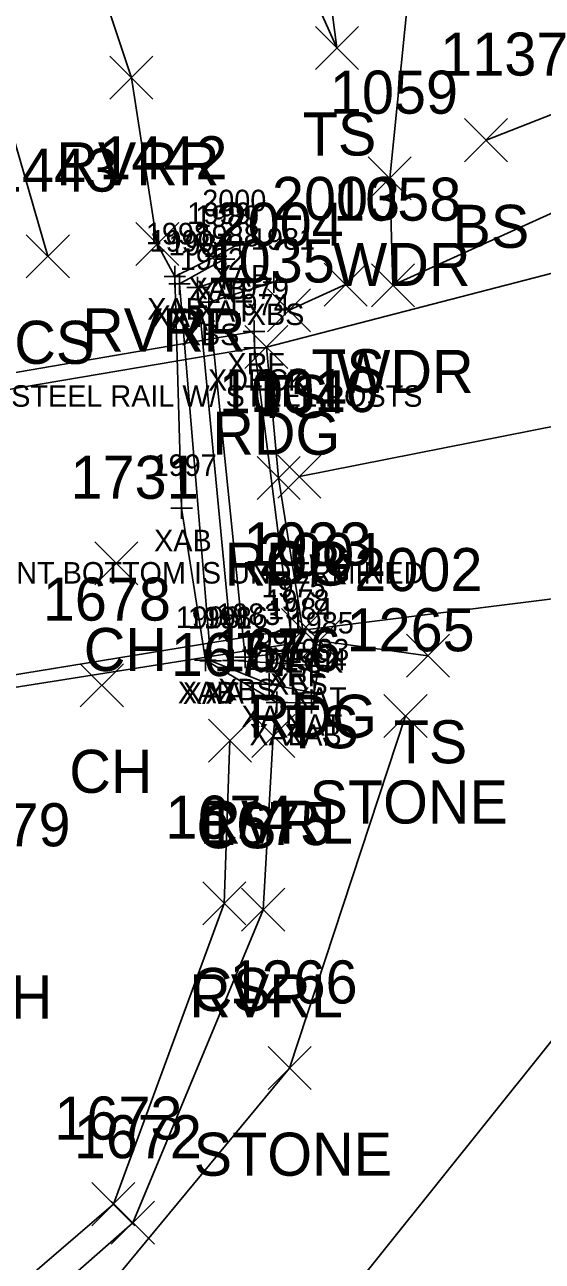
# Model space of a CAD drawing. Extents: x 1621633 to 1624015, y 417863 to 420979.
# Drawn here: x 1621985 to 1622009, y 418067.9 to 418125.3 of the extents above; entities that cross this region are included whole.
import ezdxf

# ---------------------------------------------------------------- set-up
doc = ezdxf.new("R2010")
doc.units = 0
for name, color, linetype in [('B_A', 7, 'Continuous'), ('B_C', 7, 'Continuous'), ('B_I', 7, 'Continuous'), ('B_TIC', 7, 'Continuous'), ('BELB', 7, 'Continuous'), ('BR', 7, 'Continuous'), ('BSE', 7, 'Continuous'), ('BSUBM', 7, 'Continuous'), ('L_A', 7, 'Continuous'), ('L_I', 7, 'Continuous'), ('L_TIC', 7, 'Continuous'), ('LASF', 7, 'Continuous'), ('LAWA', 7, 'Continuous'), ('LAWE', 7, 'Continuous'), ('LELB', 7, 'Continuous'), ('P_A', 7, 'Continuous'), ('P_I', 7, 'Continuous'), ('P_TIC', 7, 'Continuous'), ('PEU', 7, 'Continuous'), ('PRC', 7, 'Continuous'), ('RDW', 7, 'Continuous')]:
    doc.layers.add(name, color=color, linetype=linetype)

msp = doc.modelspace()

# ---------------------------------------------------------------- linework, layer by layer
at = {"layer": 'B_TIC'}
for p, q in [((1621994.992, 418115.159), (1621995.067, 418115.159)), ((1621993.888, 418114.568), (1621993.964, 418114.568)), ((1621994.261, 418114.427), (1621994.336, 418114.427)), ((1621991.966, 418113.622), (1621992.042, 418113.622)), ((1621992.185, 418113.283), (1621992.26, 418113.283)), ((1621993.024, 418113.11), (1621993.099, 418113.11)), ((1621994.28, 418113.527), (1621994.356, 418113.527)), ((1621996.565, 418113.372), (1621996.64, 418113.372)), ((1621993.546, 418112.437), (1621993.621, 418112.437)), ((1621995.644, 418111.077), (1621995.72, 418111.077)), ((1621995.667, 418110.32), (1621995.742, 418110.32)), ((1621992.283, 418102.865), (1621992.358, 418102.865)), ((1621997.34, 418097.222), (1621997.416, 418097.222)), ((1621997.521, 418096.593), (1621997.597, 418096.593)), ((1621993.385, 418095.803), (1621993.46, 418095.803)), ((1621993.635, 418095.778), (1621993.71, 418095.778)), ((1621994.683, 418095.792), (1621994.758, 418095.792)), ((1621995.239, 418095.942), (1621995.315, 418095.942)), ((1621997.65, 418096.2), (1621997.725, 418096.2)), ((1621998.648, 418095.545), (1621998.723, 418095.545)), ((1621996.352, 418094.696), (1621996.427, 418094.696)), ((1621998.437, 418094.296), (1621998.513, 418094.296)), ((1621996.706, 418093.845), (1621996.781, 418093.845)), ((1621998.32, 418093.831), (1621998.395, 418093.831))]:
    msp.add_line(p, q, dxfattribs=at)
for points in [[(1621994.988, 418114.659), (1621994.988, 418115.659)], [(1621993.885, 418114.068), (1621993.885, 418115.068)], [(1621994.257, 418113.927), (1621994.257, 418114.927)], [(1621994.488, 418115.159), (1621995.488, 418115.159)], [(1621993.385, 418114.568), (1621994.385, 418114.568)], [(1621993.757, 418114.427), (1621994.757, 418114.427)], [(1621991.463, 418113.622), (1621992.463, 418113.622)], [(1621991.963, 418113.122), (1621991.963, 418114.122)], [(1621992.181, 418112.783), (1621992.181, 418113.783)], [(1621993.02, 418112.61), (1621993.02, 418113.61)], [(1621994.277, 418113.027), (1621994.277, 418114.027)], [(1621996.561, 418112.872), (1621996.561, 418113.872)], [(1621991.681, 418113.283), (1621992.681, 418113.283)], [(1621992.52, 418113.11), (1621993.52, 418113.11)], [(1621993.777, 418113.527), (1621994.777, 418113.527)], [(1621996.061, 418113.372), (1621997.061, 418113.372)], [(1621993.042, 418112.437), (1621994.042, 418112.437)], [(1621993.542, 418111.937), (1621993.542, 418112.937)], [(1621995.641, 418110.577), (1621995.641, 418111.577)], [(1621995.141, 418111.077), (1621996.141, 418111.077)], [(1621995.663, 418109.82), (1621995.663, 418110.82)], [(1621995.163, 418110.32), (1621996.163, 418110.32)], [(1621992.279, 418102.365), (1621992.279, 418103.365)], [(1621991.779, 418102.865), (1621992.779, 418102.865)], [(1621997.337, 418096.722), (1621997.337, 418097.722)], [(1621996.837, 418097.222), (1621997.837, 418097.222)], [(1621997.518, 418096.093), (1621997.518, 418097.093)], [(1621995.236, 418095.442), (1621995.236, 418096.442)], [(1621997.018, 418096.593), (1621998.018, 418096.593)], [(1621997.646, 418095.7), (1621997.646, 418096.7)], [(1621992.881, 418095.803), (1621993.881, 418095.803)], [(1621993.131, 418095.778), (1621994.131, 418095.778)], [(1621993.381, 418095.303), (1621993.381, 418096.303)], [(1621993.631, 418095.278), (1621993.631, 418096.278)], [(1621994.179, 418095.792), (1621995.179, 418095.792)], [(1621994.679, 418095.292), (1621994.679, 418096.292)], [(1621994.736, 418095.942), (1621995.736, 418095.942)], [(1621997.146, 418096.2), (1621998.146, 418096.2)], [(1621998.644, 418095.045), (1621998.644, 418096.045)], [(1621996.348, 418094.196), (1621996.348, 418095.196)], [(1621998.144, 418095.545), (1621999.144, 418095.545)], [(1621995.848, 418094.696), (1621996.848, 418094.696)], [(1621998.434, 418093.796), (1621998.434, 418094.796)], [(1621996.703, 418093.345), (1621996.703, 418094.345)], [(1621997.934, 418094.296), (1621998.934, 418094.296)], [(1621998.316, 418093.331), (1621998.316, 418094.331)], [(1621996.203, 418093.845), (1621997.203, 418093.845)], [(1621997.816, 418093.831), (1621998.816, 418093.831)]]:
    msp.add_lwpolyline(points, dxfattribs=at)
at = {"layer": 'BELB'}
msp.add_lwpolyline([(1621972.279, 418106.356), (1621995.663, 418110.32), (1621997.337, 418097.222), (1621973.974, 418093.412)], dxfattribs=at)
at = {"layer": 'BR'}
for points in [[(1621995.641, 418111.077), (1621972.301, 418107.07)], [(1621974.113, 418092.897), (1621997.518, 418096.593)]]:
    msp.add_lwpolyline(points, dxfattribs=at)
at = {"layer": 'BSE'}
msp.add_lwpolyline([(1621996.561, 418113.372), (1621993.542, 418112.437), (1621995.236, 418095.942), (1621997.646, 418096.2)], dxfattribs=at)
at = {"layer": 'BSUBM'}
for points in [[(1621998.316, 418093.831), (1621996.703, 418093.845), (1621993.381, 418095.803), (1621992.279, 418102.865), (1621991.963, 418113.622), (1621993.885, 418114.568), (1621994.988, 418115.159)], [(1621998.644, 418095.545), (1621994.679, 418095.792), (1621993.02, 418113.11), (1621994.277, 418113.527), (1621994.257, 418114.427), (1621992.181, 418113.283), (1621993.631, 418095.778), (1621996.348, 418094.696), (1621998.434, 418094.296)], [(1621998.434, 418094.296), (1621998.644, 418095.545)]]:
    msp.add_lwpolyline(points, dxfattribs=at)
at = {"layer": 'L_TIC'}
for points in [[(1621998.493, 418123.246), (1622000.493, 418125.246)], [(1622000.493, 418123.246), (1621998.493, 418125.246)], [(1621988.945, 418121.858), (1621990.945, 418123.858)], [(1621990.945, 418121.858), (1621988.945, 418123.858)], [(1622005.415, 418118.96), (1622007.415, 418120.96)], [(1622007.415, 418118.96), (1622005.415, 418120.96)], [(1622000.944, 418117.19), (1622002.944, 418119.19)], [(1622002.944, 418117.19), (1622000.944, 418119.19)], [(1621990.148, 418114.143), (1621992.148, 418116.143)], [(1621992.148, 418114.143), (1621990.148, 418116.143)], [(1621985.067, 418113.571), (1621987.067, 418115.571)], [(1621987.067, 418113.571), (1621985.067, 418115.571)], [(1621998.891, 418112.252), (1622000.891, 418114.252)], [(1622000.891, 418112.252), (1621998.891, 418114.252)], [(1622001.089, 418112.22), (1622003.089, 418114.22)], [(1622003.089, 418112.22), (1622001.089, 418114.22)], [(1621996.271, 418111.058), (1621998.271, 418113.058)], [(1621998.271, 418111.058), (1621996.271, 418113.058)], [(1621988.247, 418099.302), (1621990.247, 418101.302)], [(1621990.247, 418099.302), (1621988.247, 418101.302)], [(1621997.679, 418095.712), (1621999.679, 418097.712)], [(1621999.679, 418095.712), (1621997.679, 418097.712)], [(1622002.715, 418095.016), (1622004.715, 418097.016)], [(1622004.715, 418095.016), (1622002.715, 418097.016)], [(1621987.573, 418093.644), (1621989.573, 418095.644)], [(1621989.573, 418093.644), (1621987.573, 418095.644)], [(1622001.675, 418092.219), (1622003.675, 418094.219)], [(1622003.675, 418092.219), (1622001.675, 418094.219)], [(1621993.522, 418091.07), (1621995.522, 418093.07)], [(1621995.522, 418091.07), (1621993.522, 418093.07)], [(1621995.533, 418091.287), (1621997.533, 418093.287)], [(1621997.533, 418091.287), (1621995.533, 418093.287)], [(1621993.262, 418083.512), (1621995.262, 418085.512)], [(1621995.262, 418083.512), (1621993.262, 418085.512)], [(1621995.064, 418083.217), (1621997.064, 418085.217)], [(1621997.064, 418083.217), (1621995.064, 418085.217)], [(1621996.296, 418075.86), (1621998.296, 418077.86)], [(1621998.296, 418075.86), (1621996.296, 418077.86)], [(1621988.111, 418069.538), (1621990.111, 418071.538)], [(1621990.111, 418069.538), (1621988.111, 418071.538)], [(1621989.012, 418068.674), (1621991.012, 418070.674)], [(1621991.012, 418068.674), (1621989.012, 418070.674)]]:
    msp.add_lwpolyline(points, dxfattribs=at)
at = {"layer": 'LASF'}
msp.add_lwpolyline([(1622002.675, 418093.219), (1621997.296, 418076.86), (1621980.179, 418056.204), (1621954.756, 418039.139), (1621928.826, 418024.949), (1621900.016, 418015.523), (1621882.357, 418011.741)], dxfattribs=at)
at = {"layer": 'LAWA'}
msp.add_lwpolyline([(1622320.208, 418157.076), (1622282.224, 418156.146), (1622251.71, 418155.079), (1622223.599, 418155.089), (1622209.107, 418155.31), (1622180.877, 418152.893), (1622152.121, 418150.865), (1622117.366, 418144.737), (1622094.144, 418141.694), (1622062.956, 418134.278), (1622030.014, 418125.886), (1622002.089, 418113.22), (1622001.944, 418118.19), (1622004.405, 418142.605), (1621992.552, 418166.206), (1621982.92, 418190.962), (1621974.219, 418213.574), (1621987.215, 418225.085), (1622016.711, 418238.58), (1622052.182, 418242.586)], dxfattribs=at)
at = {"layer": 'LAWE'}
for points in [[(1622323.31, 418180.927), (1622300.82, 418170.321), (1622276.309, 418168.44), (1622241.719, 418167.29), (1622221.816, 418173.507), (1622205.884, 418194.818), (1622185.967, 418220.629), (1622162.228, 418235.421), (1622129.819, 418241.701), (1622106.38, 418246.346), (1622101.428, 418250.254), (1622073.093, 418248.585), (1622043.818, 418244.163), (1622014.931, 418241.309), (1621989.871, 418234.249), (1621972.684, 418220.993), (1621964.49, 418204.329), (1621969.878, 418176.14), (1621978.907, 418154.619), (1621984.371, 418139.617), (1621989.945, 418122.858), (1621991.148, 418115.143)], [(1621991.148, 418115.143), (1621991.963, 418113.622)], [(1621996.533, 418092.287), (1621996.703, 418093.845)], [(1621694.469, 417944.857), (1621713.846, 417956.733), (1621742.172, 417966.049), (1621760.532, 417975.456), (1621777.237, 417983.398), (1621792.696, 417991.301), (1621817.095, 418001.163), (1621844.467, 418008.037), (1621871.363, 418013.308), (1621897.422, 418019.495), (1621922.912, 418028.804), (1621945.859, 418038.978), (1621969.359, 418051.535), (1621990.012, 418069.674), (1621996.064, 418084.217), (1621996.533, 418092.287)]]:
    msp.add_lwpolyline(points, dxfattribs=at)
at = {"layer": 'LELB'}
for points in [[(1621986.067, 418114.571), (1621980.007, 418135.511), (1621971.795, 418158.969), (1621964.778, 418178.351), (1621962.014, 418198.432), (1621960.296, 418210.777), (1621971.297, 418225.2), (1621983.839, 418236.143), (1622007.179, 418245.448), (1622025.653, 418246.508), (1622054.037, 418255.072), (1622065.318, 418256.151)], [(1621971.105, 418202.038), (1621979.4, 418192.232), (1621984.229, 418168.425), (1621996.449, 418147.456), (1621999.493, 418124.246), (1621994.981, 418134.297), (1621984.25, 418161.103), (1621976.078, 418182.597), (1621971.887, 418195.675)], [(1622006.415, 418119.96), (1622026.784, 418127.961), (1622037.161, 418131.419)], [(1621999.891, 418113.252), (1621997.271, 418112.058)], [(1621998.679, 418096.712), (1622003.715, 418096.016)], [(1621694.018, 417945.604), (1621713.058, 417958.392), (1621741.418, 417968.002), (1621759.92, 417977.729), (1621776.332, 417984.988), (1621792.046, 417992.579), (1621816.284, 418002.68), (1621844.088, 418009.589), (1621869.849, 418015.692), (1621896.837, 418021.913), (1621921.805, 418030.632), (1621944.897, 418041.057), (1621968.773, 418053.066), (1621989.111, 418070.538), (1621994.262, 418084.512), (1621994.522, 418092.07)]]:
    msp.add_lwpolyline(points, dxfattribs=at)
at = {"layer": 'P_TIC'}
for points in [[(1621995.214, 418109.35), (1621997.214, 418111.35)], [(1621997.214, 418109.35), (1621995.214, 418111.35)], [(1621995.78, 418103.27), (1621997.78, 418105.27)], [(1621997.78, 418103.27), (1621995.78, 418105.27)], [(1621996.748, 418103.333), (1621998.748, 418105.333)], [(1621998.748, 418103.333), (1621996.748, 418105.333)], [(1621996.915, 418096.203), (1621998.915, 418098.203)], [(1621998.915, 418096.203), (1621996.915, 418098.203)]]:
    msp.add_lwpolyline(points, dxfattribs=at)
at = {"layer": 'PEU'}
msp.add_lwpolyline([(1622194.167, 418133.578), (1622165.782, 418130.649), (1622135.81, 418126.422), (1622106.702, 418121.829), (1622082.092, 418116.179), (1622052.808, 418106.537), (1622024.042, 418100.476), (1621997.915, 418097.203), (1621996.78, 418104.27), (1621996.214, 418110.35), (1622021.077, 418116.794), (1622048.73, 418126.692), (1622081.221, 418135.215), (1622108.123, 418139.761), (1622139.716, 418144.656), (1622170.966, 418148.681), (1622202.204, 418150.62)], dxfattribs=at)
at = {"layer": 'PRC'}
msp.add_lwpolyline([(1621997.748, 418104.333), (1622030.167, 418110.754), (1622061.28, 418119.206), (1622091.298, 418126.36), (1622119.867, 418131.333), (1622150.166, 418136.531), (1622182.15, 418139.317), (1622212.387, 418141.944), (1622242.915, 418142.528), (1622274.163, 418143.677), (1622303.741, 418144.568), (1622320.756, 418144.646)], dxfattribs=at)
at = {"layer": 'RDW'}
msp.add_lwpolyline([(1621869.66, 417990.005), (1621898.189, 417999.842), (1621925.17, 418010.412), (1621952.262, 418024.445), (1621976.225, 418041.199), (1621996.59, 418062.054), (1622014.164, 418083.988), (1622019.779, 418092.569), (1622014.506, 418097.249)], dxfattribs=at)

# ---------------------------------------------------------------- texts
at = {"layer": 'B_A'}
for s, p in [('XAB', (1621993.709, 418113.159)), ('XAB', (1621992.605, 418112.568)), ('XAT', (1621992.962, 418112.427)), ('XAB', (1621990.683, 418111.622)), ('XAT', (1621992.981, 418111.527)), ('XAT', (1621990.886, 418111.283)), ('XAT', (1621991.725, 418111.11)), ('XBS', (1621995.302, 418111.372)), ('XBS', (1621992.282, 418110.437)), ('XRF', (1621994.401, 418109.077)), ('XDECK', (1621993.506, 418108.32)), ('XAB', (1621991, 418100.865)), ('XDECK', (1621995.179, 418095.222)), ('XRF', (1621996.278, 418094.593)), ('XBS', (1621996.387, 418094.2)), ('XAB', (1621992.102, 418093.803)), ('XAT', (1621992.336, 418093.778)), ('XAT', (1621993.384, 418093.792)), ('XBS', (1621993.976, 418093.942)), ('XAT', (1621997.349, 418093.545)), ('XAT', (1621995.053, 418092.696)), ('XAT', (1621997.139, 418092.296)), ('XAB', (1621995.423, 418091.845)), ('XAB', (1621997.037, 418091.831))]:
    msp.add_text(s, height=1, dxfattribs=at).set_placement(p)
at = {"layer": 'B_C'}
for s, p in [('STEEL RAIL W/ STEEL POSTS', (1621984.365, 418107.577)), ('ABUTMENT BOTTOM IS UNDERMINED', (1621979.031, 418099.365))]:
    msp.add_text(s, height=1, dxfattribs=at).set_placement(p)
at = {"layer": 'B_I'}
for s, p in [('2000', (1621993.237, 418116.659)), ('1999', (1621992.535, 418116.068)), ('1989', (1621992.907, 418115.927)), ('1998', (1621990.617, 418115.122)), ('1988', (1621992.93, 418115.027)), ('1981', (1621995.498, 418114.872)), ('1990', (1621990.791, 418114.783)), ('1987', (1621991.674, 418114.61)), ('1982', (1621992.196, 418113.937)), ('1979', (1621994.29, 418112.577)), ('1974', (1621994.317, 418111.82)), ('1997', (1621990.933, 418104.365)), ('1975', (1621995.99, 418098.722)), ('1978', (1621996.171, 418098.093)), ('1984', (1621996.3, 418097.7)), ('1996', (1621992.007, 418097.303)), ('1991', (1621992.568, 418097.278)), ('1986', (1621993.305, 418097.292)), ('1983', (1621993.889, 418097.442)), ('1985', (1621997.298, 418097.045)), ('1992', (1621995.002, 418096.196)), ('1995', (1621995.356, 418095.345)), ('1994', (1621996.97, 418095.331)), ('1993', (1621997.088, 418095.796))]:
    msp.add_text(s, height=1, dxfattribs=at).set_placement(p)
at = {"layer": 'L_A'}
for s, p in [('TS', (1621997.903, 418119.246)), ('RVRR', (1621986.457, 418117.858)), ('BS', (1622004.856, 418114.96)), ('WDR', (1621999.306, 418113.19)), ('RVRR', (1621987.66, 418110.143)), ('CS', (1621984.508, 418109.571)), ('TS', (1621998.3, 418108.252)), ('WDR', (1621999.451, 418108.22)), ('TS', (1621995.681, 418107.058)), ('CH', (1621987.735, 418095.302)), ('TS', (1621997.088, 418091.712)), ('TS', (1622002.125, 418091.016)), ('CH', (1621987.061, 418089.644)), ('STONE', (1621998.218, 418088.219)), ('CS', (1621992.963, 418087.07)), ('RVRL', (1621993.1, 418087.287)), ('CS', (1621992.703, 418079.512)), ('CH', (1621982.409, 418079.162)), ('RVRL', (1621992.63, 418079.217)), ('STONE', (1621992.839, 418071.86))]:
    msp.add_text(s, height=2, dxfattribs=at).set_placement(p)
at = {"layer": 'L_I'}
for s, p in [('1137', (1622004.289, 418122.96)), ('1059', (1621999.164, 418121.19)), ('1442', (1621988.455, 418118.143)), ('1443', (1621983.374, 418117.571)), ('2003', (1621996.474, 418116.252)), ('1058', (1621999.317, 418116.22)), ('2004', (1621993.854, 418115.058)), ('1731', (1621987.121, 418103.302)), ('2001', (1621995.828, 418099.712)), ('2002', (1622000.298, 418099.016)), ('1678', (1621985.833, 418097.644)), ('1265', (1621999.935, 418096.219)), ('1677', (1621991.782, 418095.07)), ('1676', (1621993.738, 418095.287)), ('1674', (1621991.522, 418087.512)), ('1679', (1621981.172, 418087.162)), ('1675', (1621993.323, 418087.217)), ('1266', (1621994.5, 418079.86)), ('1673', (1621986.371, 418073.538)), ('1672', (1621987.272, 418072.674))]:
    msp.add_text(s, height=2, dxfattribs=at).set_placement(p)
at = {"layer": 'P_A'}
for s, p in [('RDG', (1621993.702, 418105.35)), ('RDG', (1621994.268, 418099.27)), ('CR', (1621996.181, 418099.333)), ('RDG', (1621995.403, 418092.203))]:
    msp.add_text(s, height=2, dxfattribs=at).set_placement(p)
at = {"layer": 'P_I'}
for s, p in [('1035', (1621993.442, 418113.35)), ('1034', (1621994.008, 418107.27)), ('1010', (1621995.457, 418107.333)), ('1033', (1621995.143, 418100.203))]:
    msp.add_text(s, height=2, dxfattribs=at).set_placement(p)

doc.saveas('drawing.dxf')
